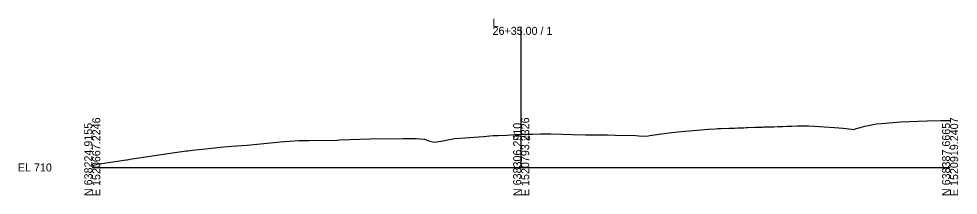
# Model space of a CAD drawing. Extents: x -26 to 3903, y -10 to 9531.
# Drawn here: x 3574.3 to 3902.8, y 490.3 to 551.9 of the extents above; entities that cross this region are included whole.
import ezdxf

# ---------------------------------------------------------------- set-up
doc = ezdxf.new("R2010")
doc.units = 0
for name, color, linetype in [('Exist Cross Section Cell', 7, 'Continuous'), ('Exist XS Center Line Elevation Label', 7, 'Continuous'), ('Exist XS Ground Line', 7, 'Continuous')]:
    doc.layers.add(name, color=color, linetype=linetype)

msp = doc.modelspace()

# ---------------------------------------------------------------- linework, layer by layer
at = {"layer": 'Exist Cross Section Cell'}
for p, q in [((3750, 500), (3750, 549.14)), ((3600, 500), (3750, 500)), ((3750, 500), (3900, 500))]:
    msp.add_line(p, q, dxfattribs=at)
at = {"layer": 'Exist XS Ground Line'}
msp.add_lwpolyline([(3600, 500.72), (3601.89, 501.11), (3611.89, 502.65), (3612.26, 502.71), (3613.18, 502.84), (3627.29, 504.99), (3632.98, 505.82), (3633.37, 505.83), (3635.11, 506), (3641.67, 506.72), (3644.74, 507.05), (3648.73, 507.41), (3654.15, 507.83), (3664.66, 508.85), (3665.69, 508.93), (3672.21, 509.39), (3675.91, 509.39), (3685.64, 509.59), (3686.59, 509.61), (3697.13, 510.03), (3708.7, 510.17), (3709.61, 510.17), (3711.39, 510.17), (3713.37, 510.13), (3714.57, 510.02), (3716.21, 509.83), (3717.69, 509.36), (3719.52, 508.78), (3721.98, 509.22), (3726.63, 510.07), (3730.33, 510.31), (3736.79, 510.81), (3740.24, 511.11), (3740.74, 511.14), (3741.23, 511.17), (3741.92, 511.18), (3744.96, 511.33), (3747.84, 511.48), (3749.42, 511.55), (3750.27, 511.59), (3750.82, 511.61), (3753.35, 511.66), (3754.02, 511.68), (3756.75, 511.74), (3758.32, 511.79), (3758.67, 511.79), (3759.59, 511.79), (3760.36, 511.78), (3764.53, 511.63), (3767.92, 511.5), (3772.53, 511.38), (3774.58, 511.36), (3779.51, 511.4), (3780.15, 511.39), (3782.87, 511.34), (3790.15, 511.16), (3791.14, 511.08), (3793.9, 510.94), (3795.02, 511.14), (3799.05, 511.8), (3802.68, 512.26), (3807.23, 512.64), (3808.9, 512.79), (3812.78, 513.11), (3815.56, 513.35), (3818.01, 513.55), (3818.8, 513.58), (3819.98, 513.62), (3822.75, 513.72), (3824.57, 513.78), (3825.72, 513.82), (3827.83, 513.9), (3828.7, 513.93), (3829.16, 513.95), (3831.67, 514.03), (3833.75, 514.1), (3834.39, 514.12), (3834.82, 514.14), (3835.99, 514.17), (3837.5, 514.21), (3837.85, 514.22), (3838.35, 514.24), (3839.71, 514.28), (3840.59, 514.31), (3841.52, 514.34), (3842.96, 514.38), (3843.56, 514.4), (3844.67, 514.43), (3846.55, 514.49), (3847.55, 514.52), (3848.68, 514.54), (3850.48, 514.59), (3852.66, 514.44), (3855.92, 514.22), (3859.58, 513.97), (3862.57, 513.68), (3865.59, 513.37), (3866.06, 513.32), (3870.21, 514.41), (3874.24, 515.27), (3877.4, 515.45), (3882.69, 515.9), (3891.94, 516.27), (3896.74, 516.35), (3900, 516.38)], dxfattribs=at)

# ---------------------------------------------------------------- texts
at = {"layer": 'Exist Cross Section Cell'}
for s, p in [('L', (3740, 549.14)), ('26+35.00 / 1', (3740, 546.34)), ('EL 710', (3574, 498.6))]:
    msp.add_text(s, height=2.8, dxfattribs=at).set_placement(p)
for s, p in [('E 1520667.2246', (3602.8, 490)), ('E 1520793.2326', (3752.8, 490)), ('E 1520919.2407', (3902.8, 490)), ('N 638224.9155', (3600, 490)), ('N 638306.2910', (3750, 490)), ('N 638387.6665', (3900, 490))]:
    msp.add_text(s, height=2.8, rotation=90, dxfattribs=at).set_placement(p)
at = {"layer": 'Exist XS Center Line Elevation Label'}
msp.add_text('721.58', height=1.5, dxfattribs=at).set_placement((3746.92, 509.58))

doc.saveas('drawing.dxf')
